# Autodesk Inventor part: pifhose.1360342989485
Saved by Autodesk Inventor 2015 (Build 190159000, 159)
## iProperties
IsCustomPart: 1
Company: Parker Hannifin
Created: 2013-02
Material: Rubber
Description: Tömlő
Document SubType Name: Modeling
Standard: Parker
Designer: Marci
Manufacturer: Parker
Language: hu-HU
Size Designation: 1/4 - 5
Categories: <MemberInstance><Categories><Category DisplayName="Csővezetékek" InternalName="4347fa0f-2144-441d-94cd-e3e15c92b736" Mnemonic="TUBEANDPIPE"><CategoryParameter D
Stock Number: Parker hidraulikatömlő - No Skive 1/4
Density: 1 g/cm^3
Appearance: Rubber - Black - Version 1.1
NAME: PIPING: Parker Hydraulic Hose - No Skive
DATA: <meta><inlinegroups number="1" deflen="12.7"></inlinegroups><connections number="2"></connections><angles><a>3.14159265358979</a></angles></meta>
L: 21,822 in
PL: 21,822 in
RPL: 21,875 in
OPL: 21,822 in
ROPL: 21,875 in
Author: Marci
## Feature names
1. Sweep1
## Parameters: ID = 6.35 mm, OD = 14.986 mm, L = 554.2788 mm, PL = 554.2788 mm, Size_Designation = 2.5 mm, d6 = 0, RPL = 555.625 mm, OPL = 554.2788 mm, ROPL = 555.625 mm, d7 = 0
